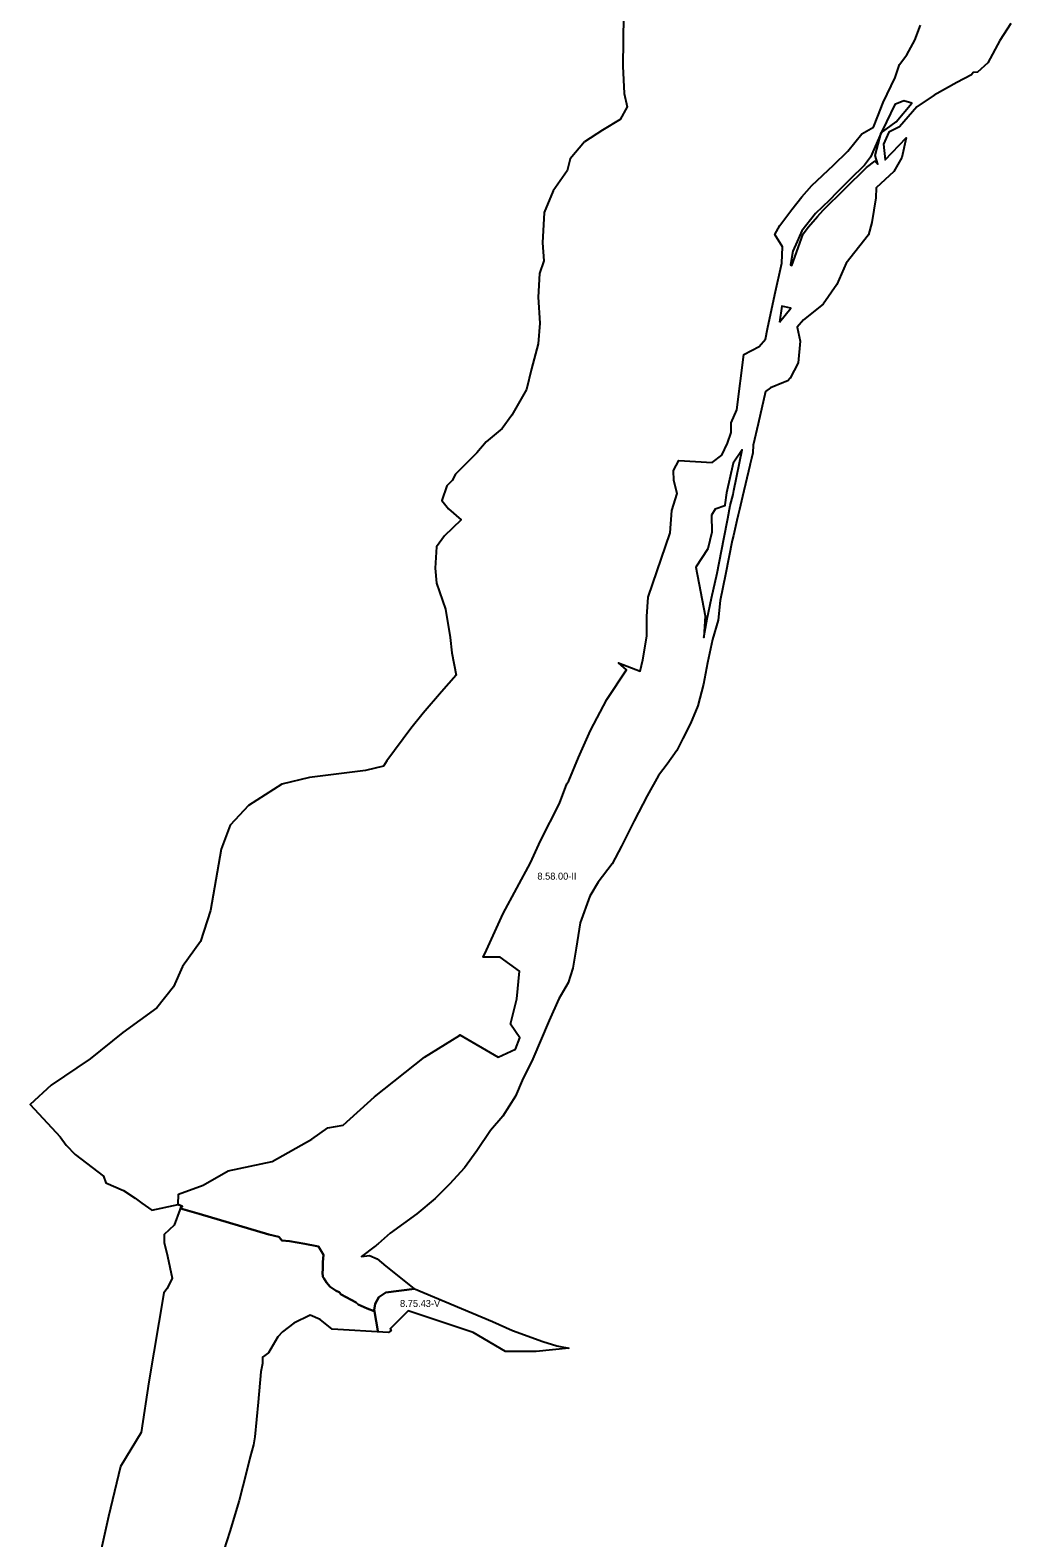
# Model space of a CAD drawing. Extents: x -547623 to -533936, y -1096714 to -1086523.
# Drawn here: x -546310 to -544894, y -1092367 to -1090189 of the extents above; entities that cross this region are included whole.
import ezdxf

# ---------------------------------------------------------------- set-up
doc = ezdxf.new("R2010")
doc.units = 0
doc.layers.add('Vrstva 27', color=7, linetype='Continuous')
doc.layers.add('Vrstva 28', color=7, linetype='Continuous')

msp = doc.modelspace()

# ---------------------------------------------------------------- linework, layer by layer
at = {"layer": 'Vrstva 28'}
for p, q in [((-546096.5, -1091885.5), (-546092, -1091887.5)), ((-546093.2, -1091891.4), (-546066, -1091899)), ((-546066, -1091899), (-545965.5, -1091929)), ((-545965.5, -1091929), (-545951, -1091932.4)), ((-545951, -1091932.4), (-545947.6, -1091935.9)), ((-545947.6, -1091935.9), (-545946.8, -1091937.4)), ((-545946.8, -1091937.4), (-545935.5, -1091938.5)), ((-545935.5, -1091938.5), (-545913.4, -1091942.3)), ((-545913.4, -1091942.3), (-545896.1, -1091945.5)), ((-545896.1, -1091945.5), (-545893.9, -1091946.1)), ((-545893.9, -1091946.1), (-545886.6, -1091958)), ((-545887.3, -1091969), (-545887.7, -1091979.3)), ((-545886.6, -1091958), (-545887.3, -1091969)), ((-545887.7, -1091979.3), (-545887.9, -1091983.6)), ((-545887.9, -1091983.6), (-545887.7, -1091989.8)), ((-545887.7, -1091989.8), (-545886.2, -1091992.1)), ((-545886.2, -1091992.1), (-545882.4, -1091998)), ((-545882.4, -1091998), (-545877.1, -1092004.6)), ((-545877.1, -1092004.6), (-545868.5, -1092010)), ((-545868.5, -1092010), (-545864, -1092012.2)), ((-545864, -1092012.2), (-545861, -1092015.5)), ((-545861, -1092015.5), (-545839.6, -1092027.1)), ((-545806.5, -1092019.5), (-545796.5, -1092012.5)), ((-545796.5, -1092012.5), (-545755, -1092007.3)), ((-545839.6, -1092027.1), (-545836.5, -1092029.8)), ((-545836.5, -1092029.8), (-545823.7, -1092035.8)), ((-545823.7, -1092035.8), (-545813.3, -1092039.7)), ((-545813.5, -1092037.9), (-545812, -1092029)), ((-545813.5, -1092038), (-545813.5, -1092037.9)), ((-545813.1, -1092039.8), (-545813.5, -1092038)), ((-545812, -1092029), (-545806.5, -1092019.5)), ((-545813.3, -1092039.7), (-545813.1, -1092039.8)), ((-545813.1, -1092039.8), (-545813, -1092040)), ((-545813, -1092040), (-545813.1, -1092039.8)), ((-545813, -1092040), (-545808, -1092068)), ((-545808, -1092068), (-545813, -1092040)), ((-545808, -1092068), (-545808.2, -1092069.7))]:
    msp.add_line(p, q, dxfattribs=at)
for points in [[(-545453.5, -1090167.7), (-545454.4, -1090241.3), (-545452.5, -1090281.1), (-545448.1, -1090300.4), (-545458.3, -1090318.5), (-545483.9, -1090333.8), (-545509.7, -1090350.7), (-545530.4, -1090375.4), (-545534.8, -1090392.8), (-545555.1, -1090421.3), (-545568.2, -1090452.8), (-545570.6, -1090496.6), (-545568.5, -1090522.6), (-545574.7, -1090540.9), (-545576.8, -1090575.2), (-545574.1, -1090612.8), (-545576.9, -1090642.4), (-545586.2, -1090678.8), (-545593.4, -1090708.5), (-545614.5, -1090745.6), (-545628.7, -1090765), (-545651.6, -1090784), (-545665.3, -1090800.1), (-545684.6, -1090819.1), (-545695.9, -1090830.9), (-545700.6, -1090840), (-545708.5, -1090847.8), (-545715.8, -1090868.8), (-545706.2, -1090880.8), (-545687.8, -1090896.7), (-545700.4, -1090908.9), (-545711.8, -1090919.7), (-545723.3, -1090935.8), (-545725.4, -1090966.3), (-545723.4, -1090988.2), (-545710.6, -1091025.7), (-545703.9, -1091066.8), (-545701.3, -1091088.6), (-545695, -1091121), (-545716.4, -1091144.9), (-545742.8, -1091175.9), (-545760.5, -1091197.9), (-545795, -1091244.6), (-545800.1, -1091252.6), (-545825.7, -1091258.5), (-545906.6, -1091268.7), (-545946.8, -1091278.4), (-545994.8, -1091309.3), (-546021.4, -1091337.6), (-546034.4, -1091372.4), (-546049.6, -1091460.9), (-546064, -1091505.8), (-546089.9, -1091541.9), (-546103.1, -1091571.1), (-546127.3, -1091601.3), (-546176.5, -1091636.9), (-546223.6, -1091675), (-546279.6, -1091713.2), (-546310, -1091741), (-546266.7, -1091787.8), (-546257.9, -1091799.7), (-546245.1, -1091813.3), (-546204.2, -1091844.6), (-546201, -1091854.3), (-546175.4, -1091865.3), (-546158.4, -1091876.4), (-546148.8, -1091883.5), (-546134.2, -1091893.5), (-546096.5, -1091885.5), (-546095.8, -1091870.6), (-546060.2, -1091857.8), (-546024.4, -1091836.9), (-545960.9, -1091823.3), (-545903.6, -1091791.2), (-545880.5, -1091775), (-545858.2, -1091770.9), (-545813, -1091729.8), (-545740.7, -1091672.5), (-545690.4, -1091641.3), (-545689.7, -1091640.4), (-545634.3, -1091672.6), (-545609.2, -1091661), (-545603.3, -1091645), (-545616.8, -1091625.2), (-545607.3, -1091588.3), (-545603.5, -1091548.5), (-545631.6, -1091528.4), (-545656.2, -1091528.4), (-545651.3, -1091518), (-545627.4, -1091465.1), (-545587.5, -1091392), (-545573.2, -1091360.1), (-545545.9, -1091306.5), (-545535.1, -1091278.1), (-545532.2, -1091273.6), (-545518.5, -1091240.1), (-545501.3, -1091200.7), (-545477.7, -1091156.3), (-545449.2, -1091113.3), (-545460.8, -1091103.1), (-545429.5, -1091115.2), (-545425.5, -1091098.7), (-545419.6, -1091064.9), (-545419.8, -1091036.3), (-545417.8, -1091008.3), (-545386.1, -1090915.5), (-545383.6, -1090883), (-545375.8, -1090858.6), (-545381, -1090840), (-545381.2, -1090825.2), (-545373.7, -1090811.2), (-545325.3, -1090813.8), (-545311.6, -1090803.3), (-545303.2, -1090785.9), (-545298.2, -1090770.6), (-545297.9, -1090756.6), (-545289.7, -1090738), (-545279.9, -1090658), (-545257.5, -1090646.4), (-545248.7, -1090635.8), (-545245.4, -1090620.7), (-545235.2, -1090571.2), (-545224.7, -1090526.2), (-545223.8, -1090502.2), (-545234.9, -1090484.8), (-545227.6, -1090471.8), (-545210.4, -1090448.5), (-545196, -1090430.1), (-545181.7, -1090413.6), (-545150.3, -1090384.6), (-545129.7, -1090364.1), (-545109.5, -1090339.2), (-545092.6, -1090329.7), (-545086.5, -1090313.9), (-545078.8, -1090293.8), (-545061.3, -1090257.6), (-545054.8, -1090238.9), (-545044.5, -1090225.1), (-545032.9, -1090204.1), (-545024.6, -1090182.3)], [(-545453.5, -1090167.7), (-545454.4, -1090241.3), (-545452.5, -1090281.1), (-545448.1, -1090300.4), (-545458.3, -1090318.5), (-545483.9, -1090333.8), (-545509.7, -1090350.7), (-545530.4, -1090375.4), (-545534.8, -1090392.8), (-545555.1, -1090421.3), (-545568.2, -1090452.8), (-545570.6, -1090496.6), (-545568.5, -1090522.6), (-545574.7, -1090540.9), (-545576.8, -1090575.2), (-545574.1, -1090612.8), (-545576.9, -1090642.4), (-545586.2, -1090678.8), (-545593.4, -1090708.5), (-545614.5, -1090745.6), (-545628.7, -1090765), (-545651.6, -1090784), (-545665.3, -1090800.1), (-545684.6, -1090819.1), (-545695.9, -1090830.9), (-545700.6, -1090840), (-545708.5, -1090847.8), (-545715.8, -1090868.8), (-545706.2, -1090880.8), (-545687.8, -1090896.7), (-545700.4, -1090908.9), (-545711.8, -1090919.7), (-545723.3, -1090935.8), (-545725.4, -1090966.3), (-545723.4, -1090988.2), (-545710.6, -1091025.7), (-545703.9, -1091066.8), (-545701.3, -1091088.6), (-545695, -1091121), (-545716.4, -1091144.9), (-545742.8, -1091175.9), (-545760.5, -1091197.9), (-545795, -1091244.6), (-545800.1, -1091252.6), (-545825.7, -1091258.5), (-545906.6, -1091268.7), (-545946.8, -1091278.4), (-545994.8, -1091309.3), (-546021.4, -1091337.6), (-546034.4, -1091372.4), (-546049.6, -1091460.9), (-546064, -1091505.8), (-546089.9, -1091541.9), (-546103.1, -1091571.1), (-546127.3, -1091601.3), (-546176.5, -1091636.9), (-546223.6, -1091675), (-546279.6, -1091713.2), (-546310, -1091741), (-546266.7, -1091787.8), (-546257.9, -1091799.7), (-546245.1, -1091813.3), (-546204.2, -1091844.6), (-546201, -1091854.3), (-546175.4, -1091865.3), (-546158.4, -1091876.4), (-546148.8, -1091883.5), (-546134.2, -1091893.5), (-546096.5, -1091885.5), (-546092, -1091887.5), (-546093.8, -1091893.4), (-546102.1, -1091915.5), (-546116.4, -1091929), (-546116.7, -1091940.3), (-546112, -1091960), (-546105.2, -1091991.7), (-546112.4, -1092006.6), (-546117, -1092013.1), (-546138.6, -1092141.8), (-546149.7, -1092215), (-546179.8, -1092263.8), (-546197.1, -1092336), (-546208.5, -1092388.3)], [(-544894.3, -1090179.9), (-544910.1, -1090204.5), (-544927.4, -1090236.5), (-544942.5, -1090250), (-544948.5, -1090250.4), (-544951, -1090253.9), (-544972.3, -1090264.9), (-545005.2, -1090283.2), (-545030.1, -1090300.2), (-545054.9, -1090328.9), (-545070.3, -1090336.7), (-545077.9, -1090354), (-545075.7, -1090376.8), (-545045.6, -1090345), (-545051.8, -1090373.2), (-545063.4, -1090393.6), (-545088.6, -1090417.1), (-545089, -1090431.4), (-545094.8, -1090467.3), (-545099.6, -1090485), (-545131.9, -1090525.9), (-545145.5, -1090556.9), (-545165.2, -1090585.4), (-545193.7, -1090607.7), (-545202.7, -1090618.6), (-545198.2, -1090638.8), (-545201.3, -1090669.8), (-545212.7, -1090692.2), (-545216.3, -1090695.7), (-545220.3, -1090697.2), (-545222.7, -1090698.2), (-545241.4, -1090706.2), (-545248.3, -1090711.2), (-545259.3, -1090757.9), (-545266.5, -1090788.9), (-545266.8, -1090800.1), (-545268.9, -1090808.1), (-545270.7, -1090815.8), (-545271.3, -1090818.4), (-545281.6, -1090862.9), (-545286, -1090881.9), (-545287.8, -1090889.4), (-545289.8, -1090897.8), (-545294.9, -1090919.4), (-545296.5, -1090926.4), (-545306.2, -1090975.5), (-545313.7, -1091013.1), (-545317, -1091041.6), (-545324.8, -1091069.4), (-545332.2, -1091103), (-545338.1, -1091134.1), (-545346.1, -1091165.2), (-545356.6, -1091191), (-545367.8, -1091212.5), (-545376.7, -1091229.6), (-545390.6, -1091249.8), (-545403.1, -1091265.7), (-545419.2, -1091295.1), (-545438.3, -1091331.6), (-545456.3, -1091368.2), (-545470, -1091393.6), (-545490, -1091420.2), (-545502.3, -1091440.4), (-545516.2, -1091478.9), (-545521.9, -1091515.5), (-545526.7, -1091544), (-545533.3, -1091565.5), (-545546.7, -1091588.3), (-545560.6, -1091619.6), (-545584.6, -1091675), (-545599.6, -1091706.5), (-545609.3, -1091729.1), (-545627.8, -1091757.8), (-545645.7, -1091778.5), (-545665.1, -1091807.9), (-545683, -1091832.7), (-545704.7, -1091856.2), (-545725.5, -1091876.8), (-545751.8, -1091898.9), (-545790.1, -1091927.1), (-545807.8, -1091942.2), (-545809, -1091943.2), (-545810.5, -1091944.5), (-545812, -1091945.8), (-545831.7, -1091960.4), (-545820.2, -1091959.3), (-545808.9, -1091964.2), (-545796.4, -1091974.6), (-545756.1, -1092006.9), (-545642.5, -1092054.4), (-545613.8, -1092067.3), (-545570, -1092083.6), (-545549.9, -1092089.7), (-545544.9, -1092090.8), (-545532.2, -1092093.1), (-545579.6, -1092097.7), (-545623.9, -1092097.9), (-545670.7, -1092070.3), (-545764.4, -1092039.1), (-545790.1, -1092064.9), (-545789, -1092067.4), (-545790.7, -1092068.7), (-545792.5, -1092070.5), (-545873.9, -1092065.8), (-545891.3, -1092051.7), (-545905.8, -1092045.3), (-545929.5, -1092056.7), (-545945.8, -1092069.2), (-545952.7, -1092076.8), (-545965.9, -1092099.9), (-545974.8, -1092106.1), (-545974.5, -1092115.3), (-545976.9, -1092127.1), (-545980.9, -1092170.8), (-545985.6, -1092221.2), (-545987.5, -1092232.8), (-545992.5, -1092249.8), (-545997.7, -1092271.5), (-546008.4, -1092313), (-546021.9, -1092357.6), (-546035, -1092398.1)], [(-545073.8, -1090321.7), (-545081.6, -1090337.9), (-545059.8, -1090321.8), (-545037.1, -1090294.8), (-545048.6, -1090291.4), (-545061.7, -1090296.9), (-545073.8, -1090321.7)], [(-545105.7, -1090384.5), (-545126.7, -1090405.2), (-545145.7, -1090424), (-545156.3, -1090435.1), (-545176.5, -1090454.4), (-545196, -1090479.5), (-545202.8, -1090494.9), (-545208.8, -1090508.7), (-545212.6, -1090528.5), (-545210.4, -1090529.3), (-545194, -1090483.8), (-545186.2, -1090473.7), (-545173.6, -1090458.6), (-545165.3, -1090449.6), (-545102.7, -1090387.8), (-545090.7, -1090378.8), (-545086.4, -1090382.8), (-545090, -1090370.7), (-545081.6, -1090337.9), (-545097.1, -1090373), (-545105.7, -1090384.5)], [(-545228.5, -1090611), (-545211.9, -1090590.8), (-545224.9, -1090588.3), (-545228.5, -1090611)], [(-545326.6, -1091009.6), (-545318.4, -1090973.7), (-545308.4, -1090923.9), (-545302.8, -1090894.9), (-545299.3, -1090876.1), (-545295, -1090860.2), (-545294.1, -1090854.5), (-545282.2, -1090795.6), (-545295.2, -1090814.6), (-545304.8, -1090857.5), (-545307.1, -1090874.8), (-545307.2, -1090876.3), (-545321.1, -1090881.3), (-545326.6, -1090889.9), (-545325.8, -1090914.4), (-545331.8, -1090938.7), (-545349, -1090965.1), (-545335.5, -1091035.3), (-545337.4, -1091066.7), (-545332.8, -1091039.8), (-545326.6, -1091009.6)], [(-545755, -1092007.3), (-545796.5, -1092012.5), (-545806.5, -1092019.5), (-545812, -1092029), (-545813.5, -1092037.9), (-545813.5, -1092038), (-545813.1, -1092039.8), (-545813.3, -1092039.7), (-545823.7, -1092035.8), (-545836.5, -1092029.8), (-545839.6, -1092027.1), (-545861, -1092015.5), (-545864, -1092012.2), (-545868.5, -1092010), (-545877.1, -1092004.6), (-545882.4, -1091998), (-545886.2, -1091992.1), (-545887.7, -1091989.8), (-545887.9, -1091983.6), (-545887.7, -1091979.3), (-545887.3, -1091969), (-545886.6, -1091958), (-545893.9, -1091946.1), (-545896.1, -1091945.5), (-545913.4, -1091942.3), (-545935.5, -1091938.5), (-545946.8, -1091937.4), (-545947.6, -1091935.9), (-545951, -1091932.4), (-545965.5, -1091929), (-546066, -1091899), (-546093, -1091891.5), (-546089.9, -1091888.4), (-546092, -1091887.5), (-546096.5, -1091885.5)], [(-545808.2, -1092069.7), (-545808, -1092068), (-545813, -1092040), (-545813.1, -1092039.8), (-545813.3, -1092039.7), (-545823.7, -1092035.8), (-545836.5, -1092029.8), (-545839.6, -1092027.1), (-545861, -1092015.5), (-545864, -1092012.2), (-545868.5, -1092010), (-545877.1, -1092004.6), (-545882.4, -1091998), (-545886.2, -1091992.1), (-545887.7, -1091989.8), (-545887.9, -1091983.6), (-545887.7, -1091979.3), (-545887.3, -1091969), (-545886.6, -1091958), (-545893.9, -1091946.1), (-545896.1, -1091945.5), (-545913.4, -1091942.3), (-545935.5, -1091938.5), (-545946.8, -1091937.4), (-545947.6, -1091935.9), (-545951, -1091932.4), (-545965.5, -1091929)]]:
    msp.add_lwpolyline(points, dxfattribs=at)

# ---------------------------------------------------------------- texts
at = {"layer": 'Vrstva 27'}
for s, p in [('8.58.00-II', (-545577.8, -1091416.3)), ('8.75.43-V', (-545776.1, -1092033.4))]:
    msp.add_text(s, height=10, dxfattribs=at).set_placement(p)

doc.saveas('drawing.dxf')
